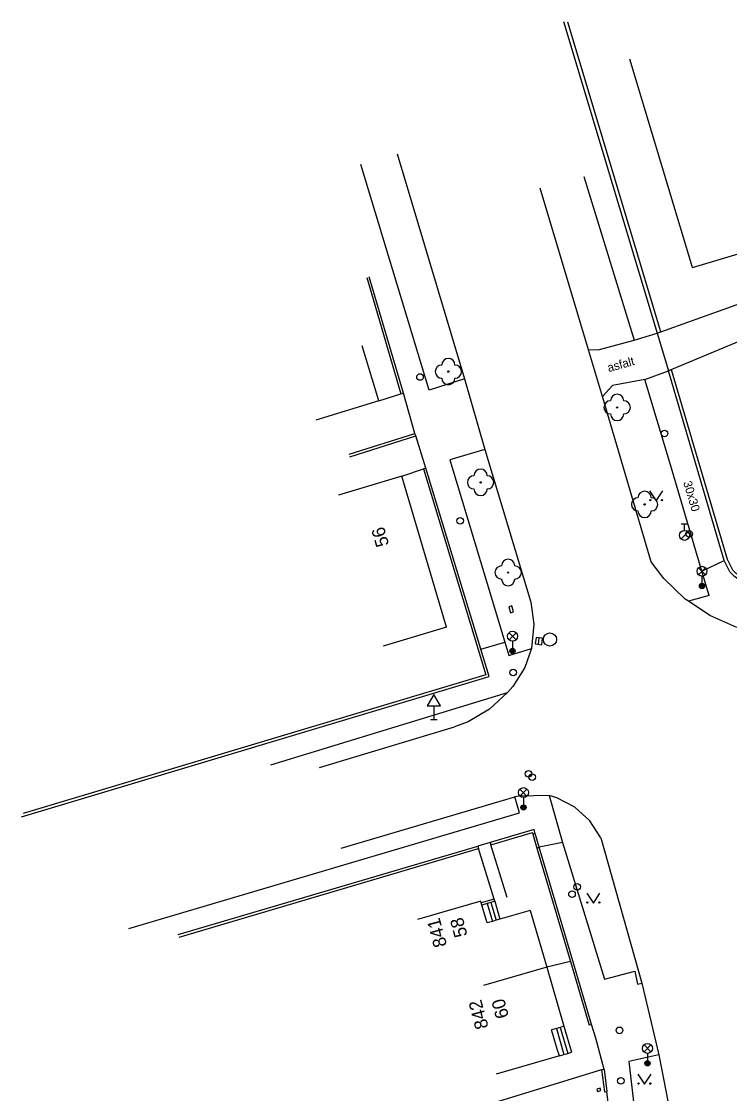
# Model space of a CAD drawing. Extents: x -539694 to -539148, y -1156467 to -1155920.
# Drawn here: x -539693.8 to -539640.2, y -1156122.8 to -1156041.6 of the extents above; entities that cross this region are included whole.
import ezdxf

# ---------------------------------------------------------------- set-up
doc = ezdxf.new("R2010")
doc.units = 0
for name, color, linetype in [('Vrstva 10', 7, 'Continuous'), ('Vrstva 11', 7, 'Continuous'), ('Vrstva 22', 7, 'Continuous'), ('Vrstva 24', 7, 'Continuous'), ('Vrstva 27', 7, 'Continuous'), ('Vrstva 28', 7, 'Continuous'), ('Vrstva 33', 7, 'Continuous'), ('Vrstva 34', 7, 'Continuous'), ('Vrstva 36', 7, 'Continuous'), ('Vrstva 40', 7, 'Continuous'), ('Vrstva 46', 7, 'Continuous'), ('Vrstva 47', 7, 'Continuous'), ('Vrstva 5', 7, 'Continuous'), ('Vrstva 6', 7, 'Continuous'), ('Vrstva 7', 7, 'Continuous'), ('Vrstva 8', 7, 'Continuous')]:
    doc.layers.add(name, color=color, linetype=linetype)

msp = doc.modelspace()

# ---------------------------------------------------------------- linework, layer by layer
at = {"layer": 'Vrstva 10'}
for p, q in [((-539671.26, -1156098.11), (-539661.01, -1156095.02)), ((-539669.61, -1156104.22), (-539656.45, -1156100.32))]:
    msp.add_line(p, q, dxfattribs=at)
for points in [[(-539639.62, -1156087.49), (-539641.674, -1156086.595), (-539643.293, -1156085.512), (-539643.537, -1156085.349), (-539645.149, -1156083.793), (-539646.11, -1156082.53)], [(-539655.24, -1156085.57), (-539654.994, -1156087.245), (-539655.18, -1156089.08), (-539655.69, -1156090.536), (-539656.592, -1156091.968), (-539657, -1156092.43)], [(-539657, -1156092.43), (-539658.369, -1156093.691), (-539659.975, -1156094.632), (-539661.01, -1156095.02)], [(-539653.84, -1156100.22), (-539656.156, -1156100.283), (-539656.45, -1156100.32)], [(-539649.93, -1156103.43), (-539650.764, -1156102.138), (-539651.902, -1156101.103), (-539653.268, -1156100.396), (-539653.84, -1156100.22)]]:
    msp.add_lwpolyline(points, dxfattribs=at)
at = {"layer": 'Vrstva 11'}
for p, q in [((-539665.372, -1156051.613), (-539660.27, -1156068.65)), ((-539662.95, -1156069.52), (-539668.12, -1156052.42)), ((-539651.21, -1156053.32), (-539647.41, -1156065.73)), ((-539650.86, -1156066.46), (-539654.53, -1156054.22)), ((-539645.372, -1156065.103), (-539630.1, -1156059.607)), ((-539647.41, -1156065.73), (-539645.66, -1156065.19)), ((-539639.46, -1156065.83), (-539644.8, -1156068.05)), ((-539649.81, -1156070), (-539650.86, -1156066.46)), ((-539646.59, -1156068.7), (-539644.8, -1156068.05)), ((-539660.27, -1156068.65), (-539662.95, -1156069.52)), ((-539660.27, -1156068.65), (-539658.72, -1156074.01)), ((-539644.65, -1156075.17), (-539646.59, -1156068.7)), ((-539646.11, -1156082.53), (-539649.81, -1156070)), ((-539658.72, -1156074.01), (-539661.36, -1156074.79)), ((-539658.72, -1156074.01), (-539655.24, -1156085.57)), ((-539661.36, -1156074.79), (-539657.2, -1156088.6)), ((-539665.01, -1156076.036), (-539663.378, -1156075.48)), ((-539642.26, -1156083.23), (-539644.65, -1156075.17)), ((-539641.71, -1156085.07), (-539643.293, -1156085.512)), ((-539656.9, -1156089.61), (-539655.18, -1156089.08)), ((-539674.95, -1156097.91), (-539657, -1156092.43)), ((-539656.09, -1156101.55), (-539656.45, -1156100.32)), ((-539685.7, -1156110.3), (-539656.09, -1156101.55)), ((-539649.93, -1156103.43), (-539646.81, -1156114.45)), ((-539658.02, -1156108.07), (-539659.193, -1156104.252)), ((-539657.03, -1156107.963), (-539658.26, -1156103.953)), ((-539652.83, -1156103.78), (-539649.64, -1156114.14)), ((-539658.257, -1156108.326), (-539657.861, -1156109.683)), ((-539657.969, -1156108.242), (-539657.574, -1156109.599)), ((-539658.545, -1156108.41), (-539658.149, -1156109.767)), ((-539646.81, -1156114.45), (-539645.52, -1156119.87)), ((-539653.296, -1156117.877), (-539652.722, -1156119.848)), ((-539653.008, -1156117.793), (-539652.434, -1156119.764)), ((-539652.72, -1156117.71), (-539652.146, -1156119.68))]:
    msp.add_line(p, q, dxfattribs=at)
for points in [[(-539650.86, -1156066.46), (-539650.04, -1156066.44), (-539647.41, -1156065.73)], [(-539646.59, -1156068.7), (-539649.04, -1156069.16), (-539649.81, -1156070)], [(-539641.71, -1156085.07), (-539642.26, -1156083.23), (-539640.57, -1156082.41)], [(-539659.017, -1156089.145), (-539657.2, -1156088.6), (-539656.9, -1156089.61)], [(-539653.84, -1156100.22), (-539652.83, -1156103.78), (-539654.592, -1156104.152)], [(-539649.64, -1156114.14), (-539647.36, -1156113.53), (-539647.14, -1156114.52), (-539646.81, -1156114.45)], [(-539653.07, -1156119.95), (-539652.722, -1156119.848), (-539652.434, -1156119.764), (-539652.146, -1156119.68)], [(-539645.52, -1156119.87), (-539647.81, -1156120.39), (-539647.39, -1156123.87), (-539645.07, -1156123.69)], [(-539645.52, -1156119.87), (-539644.8, -1156123.64), (-539645.07, -1156123.69), (-539644.5, -1156127.29)]]:
    msp.add_lwpolyline(points, dxfattribs=at)
at = {"layer": 'Vrstva 22'}
for centre in [(-539661.48, -1156068.11), (-539648.69, -1156070.82), (-539659.04, -1156076.5), (-539646.61, -1156078.17), (-539656.95, -1156083.33)]:
    msp.add_circle(centre, 0.05, dxfattribs=at)
for centre, start, end in [((-539661.98, -1156068.11), 90, 270), ((-539661.48, -1156067.61), 0, 180), ((-539660.98, -1156068.11), 270, 90), ((-539661.48, -1156068.61), 180, 0), ((-539648.69, -1156070.32), 0, 180), ((-539649.19, -1156070.82), 90, 270), ((-539648.19, -1156070.82), 270, 90), ((-539648.69, -1156071.32), 180, 0), ((-539659.04, -1156076), 0, 180), ((-539659.54, -1156076.5), 90, 270), ((-539658.54, -1156076.5), 270, 90), ((-539659.04, -1156077), 180, 0), ((-539646.61, -1156077.67), 0, 180), ((-539647.11, -1156078.17), 90, 270), ((-539646.11, -1156078.17), 270, 90), ((-539646.61, -1156078.67), 180, 0), ((-539656.95, -1156082.83), 0, 180), ((-539657.45, -1156083.33), 90, 270), ((-539656.45, -1156083.33), 270, 90), ((-539656.95, -1156083.83), 180, 0)]:
    msp.add_arc(centre, 0.5, start, end, dxfattribs=at)
at = {"layer": 'Vrstva 24'}
for p, q in [((-539656.669, -1156085.86), (-539656.91, -1156085.93)), ((-539656.91, -1156085.93), (-539656.78, -1156086.38)), ((-539656.78, -1156086.38), (-539656.539, -1156086.31)), ((-539656.539, -1156086.31), (-539656.669, -1156085.86)), ((-539655.078, -1156103.149), (-539654.905, -1156103.098)), ((-539654.765, -1156104.203), (-539654.592, -1156104.152)), ((-539649.987, -1156122.405), (-539650.226, -1156122.478)), ((-539650.226, -1156122.478), (-539650.173, -1156122.65)), ((-539650.173, -1156122.65), (-539649.934, -1156122.577)), ((-539649.934, -1156122.577), (-539649.987, -1156122.405))]:
    msp.add_line(p, q, dxfattribs=at)
at = {"layer": 'Vrstva 27'}
msp.add_line((-539654.651, -1156088.778), (-539654.589, -1156088.282), dxfattribs=at)
msp.add_lwpolyline([(-539654.403, -1156088.809), (-539654.341, -1156088.313), (-539654.837, -1156088.251), (-539654.899, -1156088.747)], close=True, dxfattribs=at)
msp.add_circle((-539653.78, -1156088.41), 0.5, dxfattribs=at)
at = {"layer": 'Vrstva 28'}
for p, q in [((-539643.84, -1156079.645), (-539643.34, -1156079.645)), ((-539643.59, -1156080.145), (-539643.59, -1156079.645)), ((-539643.848, -1156080.792), (-539643.318, -1156080.262))]:
    msp.add_line(p, q, dxfattribs=at)
for centre, radius in [((-539663.63, -1156068.52), 0.25), ((-539645.11, -1156072.79), 0.25), ((-539660.596, -1156079.411), 0.25), ((-539643.59, -1156080.52), 0.375), ((-539643.24, -1156080.41), 0.25), ((-539656.57, -1156090.91), 0.25), ((-539655.41, -1156098.58), 0.25), ((-539655.13, -1156098.84), 0.25), ((-539652.11, -1156107.7), 0.25), ((-539651.72, -1156107.15), 0.25), ((-539648.52, -1156118.02), 0.25), ((-539648.42, -1156121.85), 0.25)]:
    msp.add_circle(centre, radius, dxfattribs=at)
at = {"layer": 'Vrstva 33'}
for p, q in [((-539642.525, -1156083.5), (-539641.995, -1156082.97)), ((-539642.525, -1156082.97), (-539641.995, -1156083.5)), ((-539642.26, -1156083.61), (-539642.26, -1156084.36)), ((-539656.885, -1156088.42), (-539656.355, -1156087.89)), ((-539656.885, -1156087.89), (-539656.355, -1156088.42)), ((-539656.62, -1156088.53), (-539656.62, -1156089.28)), ((-539656.055, -1156100.27), (-539655.525, -1156099.74)), ((-539656.055, -1156099.74), (-539655.525, -1156100.27)), ((-539655.79, -1156100.38), (-539655.79, -1156101.13)), ((-539646.655, -1156119.65), (-539646.125, -1156119.12)), ((-539646.655, -1156119.12), (-539646.125, -1156119.65)), ((-539646.39, -1156119.76), (-539646.39, -1156120.51))]:
    msp.add_line(p, q, dxfattribs=at)
for centre, radius in [((-539642.26, -1156083.235), 0.375), ((-539642.26, -1156084.36), 0.2), ((-539642.26, -1156084.36), 0.145), ((-539642.26, -1156084.36), 0.0876), ((-539656.62, -1156088.155), 0.375), ((-539656.62, -1156089.28), 0.2), ((-539656.62, -1156089.28), 0.145), ((-539656.62, -1156089.28), 0.0876), ((-539655.79, -1156100.005), 0.375), ((-539655.79, -1156101.13), 0.2), ((-539655.79, -1156101.13), 0.145), ((-539655.79, -1156101.13), 0.0876), ((-539646.39, -1156119.385), 0.375), ((-539646.39, -1156120.51), 0.2), ((-539646.39, -1156120.51), 0.145), ((-539646.39, -1156120.51), 0.0876)]:
    msp.add_circle(centre, radius, dxfattribs=at)
at = {"layer": 'Vrstva 34'}
for p, q in [((-539662.59, -1156093.442), (-539662.59, -1156094.46)), ((-539662.84, -1156094.46), (-539662.34, -1156094.46))]:
    msp.add_line(p, q, dxfattribs=at)
msp.add_lwpolyline([(-539663.09, -1156093.442), (-539662.09, -1156093.442), (-539662.59, -1156092.576)], close=True, dxfattribs=at)
at = {"layer": 'Vrstva 36'}
for points in [[(-539646.23, -1156077.15), (-539645.73, -1156077.9), (-539645.23, -1156077.15)], [(-539650.99, -1156107.63), (-539650.49, -1156108.38), (-539649.99, -1156107.63)], [(-539647.12, -1156121.35), (-539646.62, -1156122.1), (-539646.12, -1156121.35)]]:
    msp.add_lwpolyline(points, dxfattribs=at)
for centre in [(-539646.18, -1156077.85), (-539645.281, -1156077.85), (-539650.94, -1156108.33), (-539650.041, -1156108.33), (-539647.07, -1156122.05), (-539646.171, -1156122.05)]:
    msp.add_circle(centre, 0.05, dxfattribs=at)
at = {"layer": 'Vrstva 5'}
for p, q in [((-539642.97, -1156060.22), (-539647.72, -1156044.43)), ((-539642.97, -1156060.22), (-539633.626, -1156057.4)), ((-539666.745, -1156070.337), (-539668.01, -1156066.148)), ((-539666.745, -1156070.337), (-539671.532, -1156071.782)), ((-539665.01, -1156076.036), (-539669.797, -1156077.481)), ((-539661.628, -1156087.474), (-539665.01, -1156076.036)), ((-539661.628, -1156087.474), (-539666.415, -1156088.919)), ((-539659.03, -1156108.23), (-539663.83, -1156109.63)), ((-539658.994, -1156108.354), (-539659.03, -1156108.23)), ((-539658.943, -1156108.526), (-539658.994, -1156108.354)), ((-539658.548, -1156109.883), (-539658.943, -1156108.526)), ((-539655.28, -1156108.93), (-539657.574, -1156109.599)), ((-539655.28, -1156108.93), (-539654.03, -1156113.22)), ((-539658.149, -1156109.767), (-539658.548, -1156109.883)), ((-539657.861, -1156109.683), (-539658.149, -1156109.767)), ((-539657.574, -1156109.599), (-539657.861, -1156109.683)), ((-539654.03, -1156113.22), (-539658.83, -1156114.62)), ((-539654.03, -1156113.22), (-539652.72, -1156117.71)), ((-539653.296, -1156117.877), (-539653.667, -1156117.986)), ((-539653.521, -1156118.49), (-539653.667, -1156117.986)), ((-539653.008, -1156117.793), (-539653.296, -1156117.877)), ((-539652.72, -1156117.71), (-539653.008, -1156117.793)), ((-539653.24, -1156119.45), (-539653.521, -1156118.49)), ((-539653.07, -1156119.95), (-539653.24, -1156119.45)), ((-539653.07, -1156119.95), (-539657.87, -1156121.35))]:
    msp.add_line(p, q, dxfattribs=at)
at = {"layer": 'Vrstva 6'}
msp.add_line((-539653.24, -1156119.45), (-539653.521, -1156118.49), dxfattribs=at)
at = {"layer": 'Vrstva 7'}
for p, q in [((-539652.751, -1156041.581), (-539645.66, -1156065.19)), ((-539645.372, -1156065.103), (-539652.419, -1156041.64)), ((-539667.674, -1156060.987), (-539665.081, -1156069.789)), ((-539664.889, -1156069.732), (-539667.482, -1156060.931)), ((-539645.66, -1156065.19), (-539645.372, -1156065.103)), ((-539644.56, -1156067.979), (-539644.8, -1156068.05)), ((-539640.57, -1156082.41), (-539644.8, -1156068.05)), ((-539640.33, -1156082.339), (-539644.56, -1156067.979)), ((-539666.745, -1156070.337), (-539665.081, -1156069.789)), ((-539665.081, -1156069.789), (-539664.889, -1156069.732)), ((-539669.007, -1156074.372), (-539664.017, -1156072.788)), ((-539668.946, -1156074.562), (-539663.956, -1156072.978)), ((-539663.956, -1156072.978), (-539664.017, -1156072.788)), ((-539663.187, -1156075.422), (-539663.378, -1156075.48)), ((-539663.378, -1156075.48), (-539658.639, -1156091.076)), ((-539693.84, -1156101.83), (-539658.39, -1156091.21)), ((-539658.639, -1156091.076), (-539693.705, -1156101.581)), ((-539654.99, -1156102.81), (-539658.31, -1156103.78)), ((-539681.96, -1156110.75), (-539659.25, -1156104.06)), ((-539681.897, -1156110.961), (-539659.193, -1156104.252)), ((-539659.25, -1156104.06), (-539659.193, -1156104.252)), ((-539658.31, -1156103.78), (-539658.26, -1156103.953)), ((-539654.765, -1156104.203), (-539652.236, -1156112.796)), ((-539652.04, -1156112.75), (-539654.592, -1156104.152)), ((-539652.236, -1156112.796), (-539654.03, -1156113.22)), ((-539652.236, -1156112.796), (-539650.813, -1156117.63)), ((-539650.64, -1156117.58), (-539652.04, -1156112.75)), ((-539650.64, -1156117.58), (-539650.813, -1156117.63)), ((-539649.868, -1156121.004), (-539659.91, -1156124.09)), ((-539649.67, -1156120.98), (-539649.868, -1156121.004)), ((-539649.868, -1156121.004), (-539649.658, -1156122.674)), ((-539649.67, -1156120.98), (-539649.46, -1156122.65)), ((-539649.658, -1156122.674), (-539649.46, -1156122.65))]:
    msp.add_line(p, q, dxfattribs=at)
for points in [[(-539658.39, -1156091.21), (-539659.017, -1156089.145), (-539663.187, -1156075.422)], [(-539637.92, -1156083.875), (-539638.344, -1156083.917), (-539639.221, -1156083.716), (-539639.656, -1156083.44), (-539639.928, -1156083.158), (-539640.33, -1156082.339)], [(-539637.87, -1156084.12), (-539638.516, -1156084.16), (-539639.431, -1156083.889), (-539639.8, -1156083.64), (-539640.157, -1156083.27), (-539640.57, -1156082.41)], [(-539658.26, -1156103.953), (-539655.112, -1156103.033), (-539655.078, -1156103.149), (-539654.765, -1156104.203)], [(-539654.592, -1156104.152), (-539654.905, -1156103.098), (-539654.99, -1156102.81)], [(-539657.969, -1156108.242), (-539658.02, -1156108.07), (-539658.994, -1156108.354)], [(-539657.969, -1156108.242), (-539658.257, -1156108.326), (-539658.545, -1156108.41), (-539658.943, -1156108.526)]]:
    msp.add_lwpolyline(points, dxfattribs=at)
at = {"layer": 'Vrstva 8'}
for p, q in [((-539645.66, -1156065.19), (-539644.8, -1156068.05)), ((-539664.017, -1156072.788), (-539664.889, -1156069.732)), ((-539663.187, -1156075.422), (-539663.956, -1156072.978)), ((-539658.31, -1156103.78), (-539659.25, -1156104.06)), ((-539650.3, -1156118.61), (-539650.64, -1156117.58)), ((-539649.67, -1156120.98), (-539650.3, -1156118.61)), ((-539649.35, -1156123.68), (-539649.46, -1156122.65))]:
    msp.add_line(p, q, dxfattribs=at)

# ---------------------------------------------------------------- texts
at = {"layer": 'Vrstva 40'}
for s, rotation, p in [('asfalt', 15.4295, (-539649.331, -1156068.151)), ('30x30', 286.51644, (-539643.69, -1156076.5))]:
    msp.add_text(s, height=0.65, rotation=rotation, dxfattribs=at).set_placement(p)
at = {"layer": 'Vrstva 46'}
for s, rotation, p in [('56', 106.47195, (-539665.959, -1156081.22)), ('58', 105.02293, (-539660.023, -1156110.822)), ('60', 105.02293, (-539656.881, -1156116.977))]:
    msp.add_text(s, height=1, rotation=rotation, dxfattribs=at).set_placement(p)
at = {"layer": 'Vrstva 47'}
for s, p in [('841', (-539661.579, -1156111.582)), ('842', (-539658.425, -1156117.782))]:
    msp.add_text(s, height=1, rotation=105.02293, dxfattribs=at).set_placement(p)

doc.saveas('drawing.dxf')
